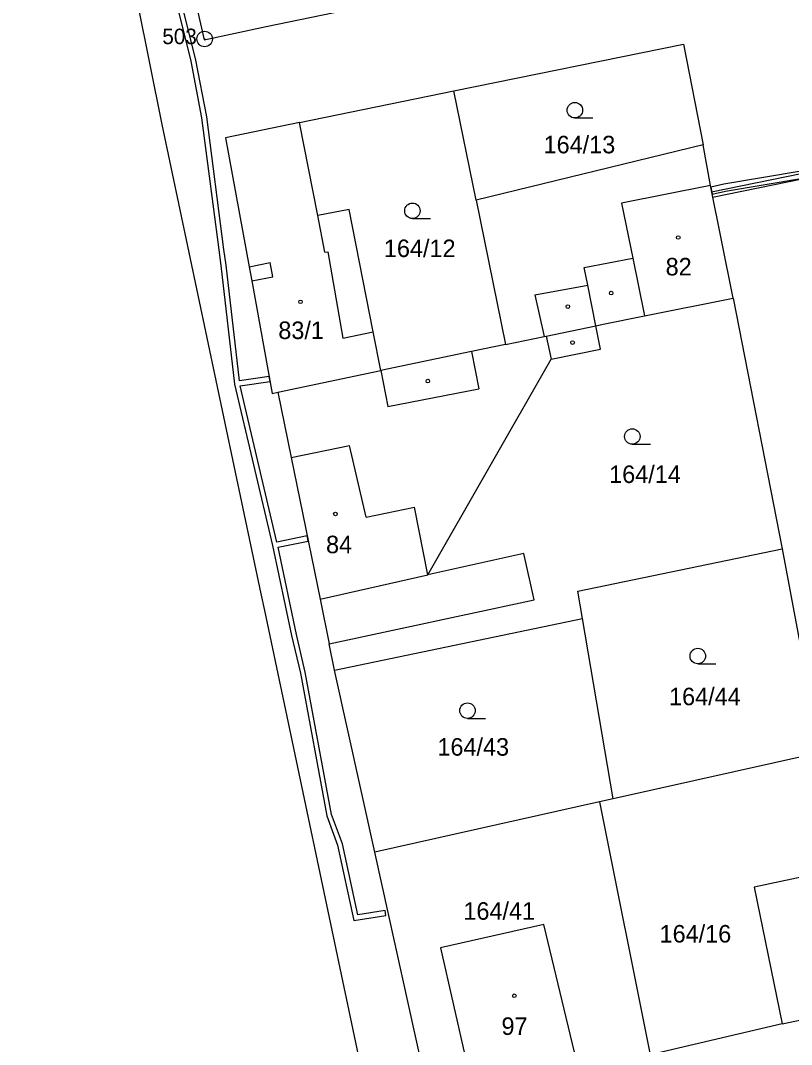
# Model space of a CAD drawing. Extents: x -779723 to -777378, y -1011169 to -1009297.
# Drawn here: x -779446.8 to -779372, y -1010276.4 to -1010177.1 of the extents above; entities that cross this region are included whole.
import ezdxf

# ---------------------------------------------------------------- set-up
doc = ezdxf.new("R2010")
doc.units = 0
for name, color, linetype in [('Hranice parcel', 7, 'Continuous'), ('Parcelní čísla', 7, 'Continuous'), ('Vnitřní kresba', 7, 'Continuous'), ('Věcná břemena k části', 7, 'Continuous'), ('Značky bodu BP', 7, 'Continuous'), ('Značky budov', 7, 'Continuous'), ('Značky kultur', 7, 'Continuous')]:
    doc.layers.add(name, color=color, linetype=linetype)

msp = doc.modelspace()

# ---------------------------------------------------------------- linework, layer by layer
at = {"layer": 'Hranice parcel'}
for p, q in [((-779419.77, -1010186.97), (-779404.79, -1010183.9)), ((-779402.63, -1010194.49), (-779404.79, -1010183.9)), ((-779380.62, -1010189.12), (-779402.63, -1010194.49)), ((-779402.63, -1010194.49), (-779399.78, -1010208.48)), ((-779377.71, -1010203.99), (-779372.96, -1010228.31)), ((-779421.87, -1010213.12), (-779411.88, -1010211.01)), ((-779372.96, -1010228.31), (-779369.26, -1010248.05)), ((-779423.51, -1010232.67), (-779423.17, -1010234.28)), ((-779423.17, -1010234.28), (-779411.57, -1010289.24)), ((-779416.36, -1010240.08), (-779392.32, -1010235.07)), ((-779389.34, -1010252.55), (-779392.32, -1010235.07)), ((-779416.36, -1010240.08), (-779416.88, -1010237.53)), ((-779412.45, -1010257.73), (-779416.36, -1010240.08)), ((-779369.26, -1010248.05), (-779389.34, -1010252.55)), ((-779389.34, -1010252.55), (-779390.67, -1010252.85)), ((-779390.67, -1010252.85), (-779412.45, -1010257.73)), ((-779390.67, -1010252.85), (-779385.75, -1010277.38)), ((-779407.72, -1010279.08), (-779412.45, -1010257.73)), ((-779372.96, -1010274.36), (-779385.75, -1010277.38))]:
    msp.add_line(p, q, dxfattribs=at)
for points in [[(-779446.83, -1010124.56), (-779439.02, -1010157.72), (-779433.12, -1010187.16), (-779423.51, -1010232.67)], [(-779433.96, -1010156.43), (-779431.85, -1010166.47), (-779431.68, -1010167.23), (-779431.65, -1010167.35), (-779429.01, -1010178.94), (-779423, -1010177.65), (-779409.96, -1010174.94)], [(-779404.79, -1010183.9), (-779382.53, -1010179.37), (-779380.62, -1010189.12)], [(-779419.77, -1010186.97), (-779426.94, -1010188.44), (-779424.65, -1010200.94), (-779424.4, -1010202.32), (-779422.41, -1010213.23), (-779421.87, -1010213.12)], [(-779411.88, -1010211.01), (-779412.61, -1010207.26), (-779414.94, -1010195.39), (-779418, -1010195.98), (-779419.77, -1010186.97)], [(-779377.71, -1010203.99), (-779379.91, -1010193.08), (-779380.62, -1010189.12)], [(-779391.03, -1010206.67), (-779390.31, -1010206.52), (-779386.3, -1010205.71), (-779377.71, -1010203.99)], [(-779416.88, -1010237.53), (-779396.99, -1010233.24), (-779397.99, -1010228.74), (-779407.33, -1010230.83), (-779395.35, -1010209.92), (-779390.58, -1010208.93), (-779391.03, -1010206.67)], [(-779399.78, -1010208.48), (-779396.04, -1010207.71), (-779395.84, -1010207.67), (-779391.03, -1010206.67)], [(-779399.78, -1010208.48), (-779403.09, -1010209.16), (-779411.88, -1010211.01)], [(-779421.87, -1010213.12), (-779420.58, -1010219.44), (-779417.77, -1010233.17), (-779416.88, -1010237.53)], [(-779392.32, -1010235.07), (-779392.78, -1010232.41), (-779372.96, -1010228.31)], [(-779366.85, -1010259.23), (-779375.67, -1010261.12), (-779372.96, -1010274.36)], [(-779372.96, -1010274.36), (-779363.99, -1010272.5), (-779366.85, -1010259.23)], [(-779398.69, -1010280.44), (-779399.16, -1010278.51), (-779393.09, -1010277.12), (-779396.07, -1010264.73), (-779406.08, -1010266.98), (-779403.57, -1010278.12), (-779407.72, -1010279.08)]]:
    msp.add_lwpolyline(points, dxfattribs=at)
at = {"layer": 'Vnitřní kresba'}
for p, q in [((-779379.91, -1010193.08), (-779388.53, -1010194.78)), ((-779388.53, -1010194.78), (-779387.44, -1010200.1)), ((-779417.3, -1010199.54), (-779418, -1010195.98)), ((-779417.3, -1010199.54), (-779417.02, -1010199.49)), ((-779417.02, -1010199.49), (-779415.55, -1010207.86)), ((-779424.65, -1010200.94), (-779422.61, -1010200.55)), ((-779422.35, -1010201.94), (-779422.61, -1010200.55)), ((-779392.14, -1010201.01), (-779387.44, -1010200.1)), ((-779387.44, -1010200.1), (-779386.3, -1010205.71)), ((-779391.8, -1010202.74), (-779392.14, -1010201.01)), ((-779424.4, -1010202.32), (-779422.35, -1010201.94)), ((-779396.93, -1010203.68), (-779391.8, -1010202.74)), ((-779391.03, -1010206.67), (-779391.8, -1010202.74)), ((-779396.93, -1010203.68), (-779396.04, -1010207.71)), ((-779415.55, -1010207.86), (-779412.61, -1010207.26)), ((-779395.84, -1010207.67), (-779395.35, -1010209.92)), ((-779403.09, -1010209.16), (-779402.38, -1010212.79)), ((-779411.88, -1010211.01), (-779411.2, -1010214.51)), ((-779411.2, -1010214.51), (-779402.38, -1010212.79)), ((-779420.58, -1010219.44), (-779414.92, -1010218.29)), ((-779413.31, -1010225.22), (-779414.92, -1010218.29)), ((-779413.31, -1010225.22), (-779408.6, -1010224.25)), ((-779407.33, -1010230.83), (-779408.6, -1010224.25)), ((-779417.77, -1010233.17), (-779407.33, -1010230.83))]:
    msp.add_line(p, q, dxfattribs=at)
at = {"layer": 'Věcná břemena k části'}
for points in [[(-779433.66, -1010167.49), (-779430.3, -1010181.02), (-779429.26, -1010186.5), (-779427.59, -1010199.32), (-779427.38, -1010200.84), (-779426.06, -1010212.32), (-779422.39, -1010227.99), (-779420.55, -1010236.71), (-779419.68, -1010240.35), (-779417.13, -1010254.2), (-779416.09, -1010257.05), (-779414.48, -1010264.34), (-779411.4, -1010263.85), (-779411.47, -1010263.36), (-779414.1, -1010263.78), (-779415.61, -1010256.91), (-779416.65, -1010254.06), (-779419.2, -1010240.25), (-779420.07, -1010236.61), (-779421.85, -1010228.14), (-779418.92, -1010227.55), (-779419.02, -1010227.05), (-779421.96, -1010227.65), (-779425.51, -1010212.49), (-779422.62, -1010212.08), (-779422.71, -1010211.59), (-779425.6, -1010212), (-779426.88, -1010200.78), (-779427.09, -1010199.26), (-779428.76, -1010186.42), (-779429.82, -1010180.92), (-779433.11, -1010167.64)], [(-779371.09, -1010191.68), (-779378.6, -1010192.95), (-779379.88, -1010193.22), (-779379.74, -1010193.9), (-779378.46, -1010193.63), (-779370.95, -1010192.36)], [(-779371.11, -1010191.94), (-779379.79, -1010193.7), (-779379.69, -1010194.2), (-779371.02, -1010192.43)]]:
    msp.add_lwpolyline(points, dxfattribs=at)
at = {"layer": 'Značky bodu BP'}
for radius in [0.75, 0.03]:
    msp.add_circle((-779428.97, -1010178.86), radius, dxfattribs=at)
at = {"layer": 'Značky budov'}
for centre in [(-779383.027, -1010198.109), (-779389.537, -1010203.499), (-779419.667, -1010204.349), (-779393.737, -1010204.809), (-779393.277, -1010208.299), (-779407.317, -1010212.039), (-779416.277, -1010224.919), (-779398.927, -1010271.639)]:
    msp.add_circle(centre, 0.175, dxfattribs=at)
at = {"layer": 'Značky kultur'}
for p, q in [((-779393.053, -1010186.52), (-779391.303, -1010186.52)), ((-779408.813, -1010196.27), (-779407.063, -1010196.27)), ((-779387.483, -1010218.16), (-779385.733, -1010218.16)), ((-779381.133, -1010239.45), (-779379.383, -1010239.45)), ((-779403.473, -1010244.74), (-779401.723, -1010244.74))]:
    msp.add_line(p, q, dxfattribs=at)
for centre in [(-779393.053, -1010185.77), (-779408.813, -1010195.52), (-779387.483, -1010217.41), (-779381.133, -1010238.7), (-779403.473, -1010243.99)]:
    msp.add_circle(centre, 0.75, dxfattribs=at)

# ---------------------------------------------------------------- texts
at = {"layer": 'Parcelní čísla'}
for s, p in [('164/13', (-779396.09, -1010189.95)), ('164/12', (-779411.58, -1010200.01)), ('82', (-779384.25, -1010201.789)), ('83/1', (-779421.82, -1010207.96)), ('164/14', (-779389.73, -1010221.919)), ('84', (-779417.19, -1010228.73)), ('164/44', (-779383.92, -1010243.47)), ('164/43', (-779406.39, -1010248.36)), ('164/41', (-779403.87, -1010264.27)), ('164/16', (-779384.84, -1010266.48)), ('97', (-779400.17, -1010275.44))]:
    msp.add_text(s, height=1.7, dxfattribs=at).set_placement(p)
at = {"layer": 'Značky bodu BP'}
msp.add_text('503', height=1.5, dxfattribs=at).set_placement((-779433.073, -1010179.36))

doc.saveas('drawing.dxf')
